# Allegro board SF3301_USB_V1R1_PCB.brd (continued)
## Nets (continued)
0: C13.1 C14.2 C15.2 C18.2 C20.2 C22.1 C23.2 C25.2 C26.2 C27.1 C28.1 C29.1 C30.1 C31.1 C32.1 C33.1 C44.2 C45.2 C46.2 C47.2 C48.2 C49.2 C50.2 C51.2 C62.2 C63.2 C64.2 C65.2 C66.2 C67.2 C68.2 C69.2 C70.2 C71.2 C72.2 C73.2 C74.2 C75.2 C76.2 C77.2 C78.2 C79.2 C80.2 C81.2 C82.2 C83.2 C84.2 C85.2 C86.2 C87.2 C88.2 C89.2 C90.2 C91.2 C92.2 C93.2 C94.2 C95.2 C96.2 C97.2 C98.2 C99.2 C100.2 C101.2 C102.2 C103.2 C104.2 C105.2 C106.2 C107.2 C108.2 C109.2 C110.2 C111.2 C112.2 C113.2 C114.2 C115.2 C116.2 C117.2 C118.2 C119.2 C120.2 C121.2 C122.2 C123.2 C124.2 C125.2 C126.2 C127.2 C128.2 C129.2 C130.2 C131.2 C132.2 C133.2 C134.2 C135.2 C136.2 C137.2 C138.2 C139.2 C140.2 C141.2 C142.2 C143.2 C144.2 C145.2 C146.2 C147.2 C148.2 C149.2 C150.2 C201.2 C202.2 C203.2 C204.2 C205.2 C206.2 C207.2 C208.2 C209.2 C210.2 C211.2 C212.2 C213.2 C214.2 C215.2 C216.2 C217.2 C218.2 C219.2 C220.2 C221.2 C222.2 C223.2 C224.2 C225.2 C226.2 C227.2 C228.2 C229.2 C230.2 C231.2 C232.2 C233.2 C234.2 C235.2 C236.2 C237.2 C238.2 C239.2 C240.2 C241.2 C242.2 C243.2 C244.2 C245.2 C246.2 C247.2 C248.2 C249.1 C250.1 C252.1 C253.1 C254.2 C255.2 C256.2 C257.2 C258.1 C260.1 C261.1 C262.1 C263.1 C264.2 C265.2 C270.1 C272.1 C273.1 C274.1 C275.1 C276.1 C278.2 C279.1 C281.1 C285.1 C287.2 C288.1 C289.1 C290.1 C291.2 C292.1 C294.1 C297.2 C298.2 C299.2 C300.2 C301.2 C302.2 C303.2 C304.2 C305.2 C306.2 C307.2 C308.2 C309.2 C310.2 C311.2 C312.2 C313.2 C314.2 C315.2 C316.2 C318.2 C319.2 C320.2 C321.1 C323.2 C324.2 C325.2 C326.2 C327.2 C328.2 C329.2 C330.2 C331.2 C333.2 C350.2 C351.2 C352.2 C353.1 C354.1 C355.1 C356.1 C357.1 C358.1 C359.2 C360.2 C363.1 C365.1 C366.2 C370.1 C372.1 C375.1 C376.1 C377.1 C378.1 C379.1 C380.1 C381.1 C387.2 C390.1 C391.1 C392.2 CP1.2 CP2.2 CP3.2 CP4.2 CP5.2 CP6.2 CP7.2 CP8.2 D2.1(A) D13.2(CATHODE) D14.2(CATHODE) D15.2(CATHODE) D16.2(CATHODE) D17.2(CATHODE) D18.2(CATHODE) D24.2(CATHODE) D25.2(CATHODE) ER2.2 ER3.2 FB7.2(FB2) FB9.2(FB2) FB11.2(FB2) J2.2 J3.5(GND) J9.1(GND1) J9.2(GND2) J10.2 J10.3 J11.1 Q3.2 Q6.1 Q6.2 Q6.3 Q7.1 Q7.2 Q7.3 Q10.1 Q10.2 Q10.3 Q11.1 Q11.2 Q11.3 Q14.1 Q14.2 Q14.3 Q15.1 Q15.2 Q15.3 Q18.1 Q18.2 Q18.3 Q19.1 Q19.2 Q19.3 Q21.1 Q21.2 Q21.3 Q23.S Q24.2 Q25.2 Q26.2 Q27.2 Q28.2 R44.2 R59.2 R60.2 R63.1 R67.2 R75.2 R77.2 R82.1 R99.1 R103.1 R107.2 R108.1 R115.1 R118.1 R122.1 R129.1 R131.1 R133.1 R135.1 R137.1 R139.1 R154.2 R191.1 R193.1 R194.1 R195.1 R196.1 R197.1 R198.1 R199.1 R203.1 R208.1 R210.1 R214.1 R217.1 R219.1 R223.1 R227.2 R241.2 R243.2 R247.1 SW1.1 SW1.3 SW1.4 TC2.2 TC3.2 TC4.2 TC5.2 TC6.2 TP3.1(PIN1) TP4.1(PIN1) TP9.1(PIN1) U3.1(GND) U5.A1(BTC_GND1) U5.A3(BTC_GND17) U5.A5(BTC_GND34) U5.A7(BTC_GND43) U5.A9(BTC_GND56) U5.A11(BTC_GND69) U5.A13(BTC_GND82) U5.A15(BTC_GND95) U5.A17(BTC_GND108) U5.A19(BTC_GND116) U5.A23(BTC_GND141) U5.AA1(LTC_GND2) U5.AA3(LTC_GND8) U5.AA5(LTC_GND16) U5.AA7(LTC_GND23) U5.AA9(LTC_GND31) U5.AA11(LTC_GND39) U5.AA13(LTC_GND47) U5.AA15(LTC_GND55) U5.AA17(LTC_GND63) U5.AA19(LTC_GND69) U5.AA21(LTC_GND78) U5.AA22(GNDE5) U5.AB2(LTC_GND6) U5.AB4(LTC_GND12) U5.AB6(LTC_GND19) U5.AB8(LTC_GND27) U5.AB10(LTC_GND35) U5.AB12(LTC_GND43) U5.AB14(LTC_GND51) U5.AB16(LTC_GND59) U5.AB18(LTC_GND66) U5.AB20(LTC_GND74) U5.AC1(LTC_GND3) U5.AC3(LTC_GND9) U5.AC5(LTC_GND17) U5.AC7(LTC_GND24) U5.AC9(LTC_GND32) U5.AC11(LTC_GND40) U5.AC13(LTC_GND48) U5.AC15(LTC_GND56) U5.AC17(LTC_GND64) U5.AC19(LTC_GND70) U5.AC21(LTC_GND79) U5.AC22(GNDE6) U5.B2(BTC_GND10) U5.B4(BTC_GND26) U5.B6(BTC_GND41) U5.B8(BTC_GND50) U5.B10(BTC_GND63) U5.B12(BTC_GND76) U5.B14(BTC_GND89) U5.B16(BTC_GND102) U5.B18(BTC_GND114) U5.B20(BTC_GND124) U5.B21(ESDSUB_ANA4) U5.B22(ESDSUB_ANA3) U5.C1(BTC_GND2) U5.C3(BTC_GND18) U5.C5(BTC_GND35) U5.C7(BTC_GND44) U5.C9(BTC_GND57) U5.C11(BTC_GND70) U5.C13(BTC_GND83) U5.C15(BTC_GND96) U5.C17(BTC_GND109) U5.C19(BTC_GND117) U5.C21(BTC_GND131) U5.C22(ESDSUB_ANA2) U5.C23(BTC_GND142) U5.D2(BTC_GND11) U5.D4(BTC_GND27) U5.D6(BTC_GND42) U5.D8(BTC_GND51) U5.D10(BTC_GND64) U5.D12(BTC_GND77) U5.D14(BTC_GND90) U5.D16(BTC_GND103) U5.D18(BTC_GND115) U5.D20(BTC_GND125) U5.D22(ESDSUB_ANA1) U5.D23(BTC_GND143) U5.E1(BTC_GND3) U5.E3(BTC_GND19) U5.E5(BTC_GND36) U5.E7(BTC_GND45) U5.E9(BTC_GND58) U5.E11(BTC_GND71) U5.E13(BTC_GND84) U5.E15(BTC_GND97) U5.E17(BTC_GND110) U5.E19(BTC_GND118) U5.E21(BTC_GND132) U5.E22(BTC_GND138) U5.F2(BTC_GND12) U5.F4(BTC_GND28) U5.F20(BTC_GND126) U5.F21(AGNDSUB_OSC) U5.F22(GNDA_OSC) U5.G1(BTC_GND4) U5.G3(BTC_GND20) U5.G5(BTC_GND37) U5.G7(BTC_GND46) U5.G9(BTC_GND59) U5.G11(BTC_GND72) U5.G13(BTC_GND85) U5.G15(BTC_GND98) U5.G17(BTC_GND111) U5.G19(BTC_GND119) U5.G21(BTC_GND133) U5.H2(BTC_GND13) U5.H4(BTC_GND29) U5.H8(BTC_GND52) U5.H10(BTC_GND65) U5.H12(BTC_GND78) U5.H14(BTC_GND91) U5.H16(BTC_GND104) U5.H20(BTC_GND127) U5.H22(BTC_GND139) U5.H23(GNDE7) U5.J1(BTC_GND5) U5.J3(BTC_GND21) U5.J5(BTC_GND38) U5.J7(BTC_GND47) U5.J9(BTC_GND60) U5.J11(BTC_GND73) U5.J13(BTC_GND86) U5.J15(BTC_GND99) U5.J17(BTC_GND112) U5.J19(BTC_GND120) U5.J21(BTC_GND134) U5.K2(BTC_GND14) U5.K4(BTC_GND30) U5.K8(BTC_GND53) U5.K10(BTC_GND66) U5.K12(BTC_GND79) U5.K14(BTC_GND92) U5.K16(BTC_GND105) U5.K20(BTC_GND128) U5.K22(GNDE1) U5.L1(BTC_GND6) U5.L3(BTC_GND22) U5.L5(BTC_GND39) U5.L7(BTC_GND48) U5.L9(BTC_GND61) U5.L11(BTC_GND74) U5.L13(BTC_GND87) U5.L15(BTC_GND100) U5.L17(BTC_GND113) U5.L19(BTC_GND121) U5.L21(BTC_GND135) U5.M2(BTC_GND15) U5.M4(BTC_GND31) U5.M8(BTC_GND54) U5.M10(BTC_GND67) U5.M12(BTC_GND80) U5.M14(BTC_GND93) U5.M16(BTC_GND106) U5.M19(BTC_GND122) U5.M20(BTC_GND129) U5.M22(BTC_GND140) U5.N1(BTC_GND7) U5.N3(BTC_GND23) U5.N5(BTC_GND40) U5.N7(BTC_GND49) U5.N9(BTC_GND62) U5.N11(BTC_GND75) U5.N13(BTC_GND88) U5.N15(BTC_GND101) U5.N21(BTC_GND136) U5.P4(BTC_GND32) U5.P8(BTC_GND55) U5.P10(BTC_GND68) U5.P12(BTC_GND81) U5.P14(BTC_GND94) U5.P16(BTC_GND107) U5.P21(BTC_GND137) U5.P22(GNDE2) U5.R1(BTC_GND8) U5.R3(BTC_GND24) U5.R5(LTC_GND13) U5.R7(LTC_GND20) U5.R9(LTC_GND28) U5.R11(LTC_GND36) U5.R13(LTC_GND44) U5.R15(LTC_GND52) U5.R17(LTC_GND60) U5.R19(BTC_GND123) U5.R20(BTC_GND130) U5.R21(LTC_GND75) U5.T2(BTC_GND16) U5.T4(BTC_GND33) U5.T8(LTC_GND25) U5.T10(LTC_GND33) U5.T12(LTC_GND41) U5.T14(LTC_GND49) U5.T16(LTC_GND57) U5.T20(LTC_GND71) U5.T22(GNDE3) U5.U1(BTC_GND9) U5.U3(BTC_GND25) U5.U5(LTC_GND14) U5.U7(LTC_GND21) U5.U9(LTC_GND29) U5.U11(LTC_GND37) U5.U13(LTC_GND45) U5.U15(LTC_GND53) U5.U17(LTC_GND61) U5.U19(LTC_GND67) U5.U21(LTC_GND76) U5.V2(LTC_GND4) U5.V4(LTC_GND10) U5.V20(LTC_GND72) U5.V22(LTC_GND80) U5.W1(LTC_GND1) U5.W3(LTC_GND7) U5.W5(LTC_GND15) U5.W7(LTC_GND22) U5.W9(LTC_GND30) U5.W11(LTC_GND38) U5.W13(LTC_GND46) U5.W15(LTC_GND54) U5.W17(LTC_GND62) U5.W19(LTC_GND68) U5.W21(LTC_GND77) U5.Y2(LTC_GND5) U5.Y4(LTC_GND11) U5.Y6(LTC_GND18) U5.Y8(LTC_GND26) U5.Y10(LTC_GND34) U5.Y12(LTC_GND42) U5.Y14(LTC_GND50) U5.Y16(LTC_GND58) U5.Y18(LTC_GND65) U5.Y20(LTC_GND73) U5.Y22(GNDE4) U6.11(GND) U7.2(GND) U8.6(GND) U9.6(GND) U10.6(GND) U11.41(PAD) U12.6(GND) U13.33(GND) U14.3(GND) U14.6(LV) U18.1(VSS) U19.2(GND) U19.25(PAD) U20.4(GND) U20.9(THER) X1.2(GND)
6314_ISEN: C361.2 L6.2 Q20.1(SOURCE1) Q20.2(SOURCE2) Q20.3(SOURCE3) Q21.5 Q21.6 Q21.7 Q21.8 R190.1 R201.2 R202.1 U13.24(PHASE)
6314_ISEN-: C362.1 C364.2 R202.2 R204.2 U13.15(ISEN-)
ADJ_TP: C276.2 R59.1 R60.1 R76.2
BTC_GNDS_0: C38.1 J6.1 J6.3 J6.5 U5.A20(BTC_GNDS_0)
BTC_GNDS_1: C39.1 J8.1 J8.3 J8.5 U5.P1(BTC_GNDS_1)
BTC_PGD: R127.2 R152.2 R181.2 R233.2
BTC_VDD: C46.1 C47.1 C48.1 C49.1 C50.1 C51.1 C62.1 C63.1 C64.1 C65.1 C66.1 C67.1 C68.1 C69.1 C70.1 C71.1 C72.1 C73.1 C74.1 C75.1 C76.1 C77.1 C78.1 C79.1 C80.1 C81.1 C82.1 C83.1 C84.1 C85.1 C86.1 C87.1 C88.1 C89.1 C90.1 C91.1 C92.1 C93.1 C94.1 C95.1 C96.1 C97.1 C98.1 C99.1 C100.1 C101.1 C102.1 C103.1 C104.1 C105.1 C106.1 C107.1 C108.1 C109.1 C110.1 C111.1 C112.1 C113.1 C114.1 C115.1 C116.1 C117.1 C118.1 C119.1 C120.1 C121.1 C122.1 C123.1 C124.1 C125.1 C126.1 C127.1 C128.1 C129.1 C130.1 C131.1 C132.1 C133.1 C134.1 C135.1 C136.1 C137.1 C138.1 C139.1 C140.1 C141.1 C142.1 C143.1 C144.1 C145.1 C146.1 C147.1 C148.1 C149.1 C150.1 C280.1 C282.1 C283.1 C284.1 C297.1 C298.1 C299.1 C300.1 C301.1 C302.1 C303.1 C304.1 C305.1 C306.1 C307.1 C308.1 C309.1 C310.1 C311.1 C312.1 C313.1 C314.1 C315.1 C316.1 CP3.1 CP4.1 CP5.1 CP6.1 D6.A L1.1 L3.1 L4.1 L5.1 R70.1 R89.1 R92.1 R95.1 TC2.1 TC3.1 TC4.1 TC5.1 U5.A2(BTC_VDD8) U5.A4(BTC_VDD25) U5.A6(BTC_VDD41) U5.A8(BTC_VDD50) U5.A10(BTC_VDD63) U5.A12(BTC_VDD76) U5.A14(BTC_VDD89) U5.A16(BTC_VDD102) U5.A18(BTC_VDD116) U5.B1(BTC_VDD1) U5.B3(BTC_VDD17) U5.B5(BTC_VDD34) U5.B7(BTC_VDD44) U5.B9(BTC_VDD57) U5.B11(BTC_VDD70) U5.B13(BTC_VDD83) U5.B15(BTC_VDD96) U5.B17(BTC_VDD109) U5.B19(BTC_VDD119) U5.C2(BTC_VDD9) U5.C4(BTC_VDD26) U5.C6(BTC_VDD42) U5.C8(BTC_VDD51) U5.C10(BTC_VDD64) U5.C12(BTC_VDD77) U5.C14(BTC_VDD90) U5.C16(BTC_VDD103) U5.C18(BTC_VDD117) U5.C20(BTC_VDD124) U5.D1(BTC_VDD2) U5.D3(BTC_VDD18) U5.D5(BTC_VDD35) U5.D7(BTC_VDD45) U5.D9(BTC_VDD58) U5.D11(BTC_VDD71) U5.D13(BTC_VDD84) U5.D15(BTC_VDD97) U5.D17(BTC_VDD110) U5.D19(BTC_VDD120) U5.D21(BTC_VDD129) U5.E2(BTC_VDD10) U5.E4(BTC_VDD27) U5.E6(BTC_VDD43) U5.E8(BTC_VDD52) U5.E10(BTC_VDD65) U5.E12(BTC_VDD78) U5.E14(BTC_VDD91) U5.E16(BTC_VDD104) U5.E18(BTC_VDD118) U5.E20(BTC_VDD125) U5.F1(BTC_VDD3) U5.F3(BTC_VDD19) U5.F5(BTC_VDD36) U5.F19(BTC_VDD121) U5.G2(BTC_VDD11) U5.G4(BTC_VDD28) U5.G8(BTC_VDD53) U5.G10(BTC_VDD66) U5.G12(BTC_VDD79) U5.G14(BTC_VDD92) U5.G16(BTC_VDD105) U5.G20(BTC_VDD126) U5.H1(BTC_VDD4) U5.H3(BTC_VDD20) U5.H5(BTC_VDD37) U5.H7(BTC_VDD46) U5.H9(BTC_VDD59) U5.H11(BTC_VDD72) U5.H13(BTC_VDD85) U5.H15(BTC_VDD98) U5.H17(BTC_VDD111) U5.H19(BTC_VDD122) U5.H21(BTC_VDD130) U5.J2(BTC_VDD12) U5.J4(BTC_VDD29) U5.J8(BTC_VDD54) U5.J10(BTC_VDD67) U5.J12(BTC_VDD80) U5.J14(BTC_VDD93) U5.J16(BTC_VDD106) U5.J20(BTC_VDD127) U5.K1(BTC_VDD5) U5.K3(BTC_VDD21) U5.K5(BTC_VDD38) U5.K7(BTC_VDD47) U5.K9(BTC_VDD60) U5.K11(BTC_VDD73) U5.K13(BTC_VDD86) U5.K15(BTC_VDD99) U5.K17(BTC_VDD112) U5.K19(BTC_VDD123) U5.K21(BTC_VDD131) U5.L2(BTC_VDD13) U5.L4(BTC_VDD30) U5.L8(BTC_VDD55) U5.L10(BTC_VDD68) U5.L12(BTC_VDD81) U5.L14(BTC_VDD94) U5.L16(BTC_VDD107) U5.L20(BTC_VDD128) U5.M1(BTC_VDD6) U5.M3(BTC_VDD22) U5.M5(BTC_VDD39) U5.M7(BTC_VDD48) U5.M9(BTC_VDD61) U5.M11(BTC_VDD74) U5.M13(BTC_VDD87) U5.M15(BTC_VDD100) U5.M17(BTC_VDD113) U5.M21(BTC_VDD132) U5.N2(BTC_VDD14) U5.N4(BTC_VDD31) U5.N8(BTC_VDD56) U5.N10(BTC_VDD69) U5.N12(BTC_VDD82) U5.N14(BTC_VDD95) U5.N16(BTC_VDD108) U5.N17(BTC_VDD114) U5.N22(BTC_VDD133) U5.P3(BTC_VDD23) U5.P5(BTC_VDD40) U5.P7(BTC_VDD49) U5.P9(BTC_VDD62) U5.P11(BTC_VDD75) U5.P13(BTC_VDD88) U5.P15(BTC_VDD101) U5.P17(BTC_VDD115) U5.R2(BTC_VDD15) U5.R4(BTC_VDD32) U5.T1(BTC_VDD7) U5.T3(BTC_VDD24) U5.U2(BTC_VDD16) U5.U4(BTC_VDD33)
BTC_VDDS_0: C38.2 J5.1 J5.3 J5.5 U5.A21(BTC_VDDS_0)
BTC_VDDS_1: C39.2 J7.1 J7.3 J7.5 U5.P2(BTC_VDDS_1)
DNRX0: R25.2 R33.1 U5.R22(DNRX0)
DNRX1: R27.2 R41.1 U5.U23(DNRX1)
DNTX0: R26.2 R35.1 U5.R23(DNTX0)
DNTX1: R29.2 R37.1 U5.U22(DNTX1)
FB_VSS: C271.1 R122.2 U11.3(FBRTN)
ISL6314_VID0: R199.2 U13.31(VID0)
ISL6314_VID1: R198.2 U13.30(VID1)
ISL6314_VID2: R197.2 U13.29(VID2)
ISL6314_VID3: R196.2 U13.28(VID3)
ISL6314_VID4: R195.2 U13.27(VID4)
ISL6314_VID5: R194.2 U13.26(VID5)
ISL6314_VID6: R193.2 U13.25(VID6)
ISL6314_VID7: R191.2 U13.32(VID7)
ISN1: R85.2 R95.2 U11.18(ISN1)
ISN24: R87.2 R92.2 U11.19(ISN24)
ISN35: R79.2 R89.2 U11.20(ISN35)
ISP1: C284.2 R96.2 U11.25(ISP1)
ISP2: C283.2 R93.2 U11.24(ISP2)
ISP3: C282.2 R90.2 U11.23(ISP3)
ISP4: C280.2 R86.2 U11.22(ISP4)
ISP5: R103.2 U11.21(ISP5)
LTC_PGD: R110.2 R173.1
LTC_PGD_R: C359.1 R143.2 R173.2 U13.1(PGOOD)
LTC_VDD: C201.1 C202.1 C203.1 C204.1 C205.1 C206.1 C207.1 C208.1 C209.1 C210.1 C211.1 C212.1 C213.1 C214.1 C215.1 C216.1 C217.1 C218.1 C219.1 C220.1 C221.1 C222.1 C223.1 C224.1 C225.1 C226.1 C227.1 C228.1 C229.1 C230.1 C231.1 C232.1 C233.1 C234.1 C235.1 C236.1 C237.1 C238.1 C239.1 C240.1 C241.1 C242.1 C243.1 C244.1 C245.1 C246.1 C247.1 C248.1 C323.1 C324.1 C325.1 C362.2 C365.2 CP7.1 L6.1 R206.1 R208.2 TC6.1 U5.AA2(LTC_VDD5) U5.AA4(LTC_VDD11) U5.AA6(LTC_VDD18) U5.AA8(LTC_VDD26) U5.AA10(LTC_VDD34) U5.AA12(LTC_VDD42) U5.AA14(LTC_VDD50) U5.AA16(LTC_VDD58) U5.AA18(LTC_VDD64) U5.AA20(LTC_VDD72) U5.AB1(LTC_VDD3) U5.AB3(LTC_VDD9) U5.AB5(LTC_VDD16) U5.AB7(LTC_VDD22) U5.AB9(LTC_VDD30) U5.AB11(LTC_VDD38) U5.AB13(LTC_VDD46) U5.AB15(LTC_VDD54) U5.AB17(LTC_VDD62) U5.AB19(LTC_VDD69) U5.AB21(LTC_VDD77) U5.AC2(LTC_VDD6) U5.AC4(LTC_VDD12) U5.AC6(LTC_VDD19) U5.AC8(LTC_VDD27) U5.AC10(LTC_VDD35) U5.AC12(LTC_VDD43) U5.AC14(LTC_VDD51) U5.AC16(LTC_VDD59) U5.AC18(LTC_VDD65) U5.AC20(LTC_VDD73) U5.R8(LTC_VDD23) U5.R10(LTC_VDD31) U5.R12(LTC_VDD39) U5.R14(LTC_VDD47) U5.R16(LTC_VDD55) U5.T5(LTC_VDD13) U5.T7(LTC_VDD20) U5.T9(LTC_VDD28) U5.T11(LTC_VDD36) U5.T13(LTC_VDD44) U5.T15(LTC_VDD52) U5.T17(LTC_VDD60) U5.T19(LTC_VDD66) U5.T21(LTC_VDD74) U5.U8(LTC_VDD24) U5.U10(LTC_VDD32) U5.U12(LTC_VDD40) U5.U14(LTC_VDD48) U5.U16(LTC_VDD56) U5.U20(LTC_VDD70) U5.V1(LTC_VDD1) U5.V3(LTC_VDD7) U5.V5(LTC_VDD14) U5.V19(LTC_VDD67) U5.V21(LTC_VDD75) U5.W2(LTC_VDD4) U5.W4(LTC_VDD10) U5.W6(LTC_VDD17) U5.W8(LTC_VDD25) U5.W10(LTC_VDD33) U5.W12(LTC_VDD41) U5.W14(LTC_VDD49) U5.W16(LTC_VDD57) U5.W18(LTC_VDD63) U5.W20(LTC_VDD71) U5.W22(LTC_VDD78) U5.Y1(LTC_VDD2) U5.Y3(LTC_VDD8) U5.Y5(LTC_VDD15) U5.Y7(LTC_VDD21) U5.Y9(LTC_VDD29) U5.Y11(LTC_VDD37) U5.Y13(LTC_VDD45) U5.Y15(LTC_VDD53) U5.Y17(LTC_VDD61) U5.Y19(LTC_VDD68) U5.Y21(LTC_VDD76) U13.16(ISEN+)
OSC_BP: R39.1 R44.1 U5.P23(OSC_BP)
OSC_EN: C354.2 Q24.3 R183.1 R186.2 X1.1(OE)
OSC_ZO: R38.2 U5.E23(OSC_ZO)
PSU_12V: C255.1 C256.1 C326.1 D8.A J9.3(12V_1) J9.4(12V_2) L2.2
PWM1: U8.2(PWM) U11.26(PWM1)
PWM2: U9.2(PWM) U11.27(PWM2)
PWM3: U10.2(PWM) U11.28(PWM3)
PWM4: U11.29(PWM4) U12.2(PWM)
PWM5: R83.2 U11.30(PWM5)
RST_SF3301: C356.2 D19.A Q26.3 R28.2 R220.2 SW1.2 U5.M23(RSTN)
RT8802A_PHASE1: C251.1 L1.2 Q4.1(SOURCE1) Q4.2(SOURCE2) Q4.3(SOURCE3) Q5.1(SOURCE1) Q5.2(SOURCE2) Q5.3(SOURCE3) Q6.5 Q6.6 Q6.7 Q6.8 Q7.5 Q7.6 Q7.7 Q7.8 R61.2 R96.1 U8.7(PHASE)
RT8802A_PHASE2: C259.1 L3.2 Q8.1(SOURCE1) Q8.2(SOURCE2) Q8.3(SOURCE3) Q9.1(SOURCE1) Q9.2(SOURCE2) Q9.3(SOURCE3) Q10.5 Q10.6 Q10.7 Q10.8 Q11.5 Q11.6 Q11.7 Q11.8 R66.2 R93.1 U9.7(PHASE)
RT8802A_PHASE3: C277.1 L4.2 Q12.1(SOURCE1) Q12.2(SOURCE2) Q12.3(SOURCE3) Q13.1(SOURCE1) Q13.2(SOURCE2) Q13.3(SOURCE3) Q14.5 Q14.6 Q14.7 Q14.8 Q15.5 Q15.6 Q15.7 Q15.8 R78.2 R90.1 U10.7(PHASE)
RT8802A_PHASE4: C286.1 L5.2 Q16.1(SOURCE1) Q16.2(SOURCE2) Q16.3(SOURCE3) Q17.1(SOURCE1) Q17.2(SOURCE2) Q17.3(SOURCE3) Q18.5 Q18.6 Q18.7 Q18.8 Q19.5 Q19.6 Q19.7 Q19.8 R86.1 R109.2 U12.7(PHASE)
RUN_LED: D1.C1 U19.22(GPIO.2_SCI/RSR_SCI)
UART1_RX: R49.2 U6.3(A2)
UART1_RX_3V3: R9.2 U19.12(RXD_ECI)
UART1_TX: R48.2 U6.1(A1)
UART1_TX_3V3: R8.2 U19.13(TXD_ECI)
UART2_RX: R51.2 U6.5(A4)
UART2_RX_3V3: R11.2 U19.20(RXD_SCI)
UART2_TX: R50.2 U6.4(A3)
UART2_TX_3V3: R10.2 U19.21(TXD_SCI)
UPRX0: R48.1 R174.2 U5.J22(UPRX0)
UPRX1: R50.1 R175.2 U5.L23(UPRX1)
UPTX0: R46.2 R49.1 U5.J23(UPTX0)
UPTX1: R47.2 R51.1 U5.L22(UPTX1)
USB_DM: R23.1 U19.4(D-)
USB_DP: R24.1 U19.3(D+)
VCORE: D6.C R79.1 R82.2 R85.1 R87.1
VID0: R80.1 R128.1 R129.2 U11.39(VID0)
VID1: R81.1 R130.1 R131.2 U11.38(VID1)
VID2: R88.1 R132.1 R133.2 U11.37(VID2)
VID3: R91.1 R134.1 R135.2 U11.36(VID3)
VID4: R94.1 R136.1 R137.2 U11.35(VID4)
VID5: R97.1 R138.1 R139.2 U11.34(VID5)
VID6: R98.1 R244.1 R247.2 U11.33(VID6)
VID7: R99.2 R245.1 R248.1 U11.32(VID7)
XCLKIN: R184.1 R185.2 U5.F23(XCLKIN)
N16884499: C18.1 R32.1 R185.1 Y2.2
N16884503: C20.1 R32.2 R38.1 Y2.1
N16885409: TP10.1(PIN1) U5.V23(DBG)
N16885936: R178.2 U5.K23(XCLKOUT)
N16887961: R45.2 U5.AA23(ANAREXTPAD)
N16887964: ER2.1 R45.1 U5.AB23(GNDBGCOMP)
N16971828: Q6.4(GATE) Q7.4(GATE) U8.5(LGATE)
N16972086: Q10.4(GATE) Q11.4(GATE) U9.5(LGATE)
N16972137: Q8.4(GATE) Q9.4(GATE) U9.8(UGATE)
N16972188: C267.2 R68.2 U11.5(COMP)
N16972208: C268.2 R68.1
N16972210: C267.1 C268.1 C269.2 R69.2 U11.4(FB)
N16972290: C287.1 R102.1 U11.31(VDD)
N16972304: C270.2 R66.1
N16972345: C265.1 U11.6(SS)
N16972387: R67.1 R71.2 U11.16(TCOC)
N16972391: D4.C R65.2 U9.1(BOOT)
N16972393: C264.1 D4.A R64.1 U9.4(VCC)
N16972419: R71.1 U11.17(IMAX)
N16972439: Q4.4(GATE) Q5.4(GATE) U8.8(UGATE)
N16972492: C259.2 R65.1
N16972578: R115.2 U11.7(QRSEL)
N16972692: C292.2 R105.2 U11.10(TSET)
N16972744: Q14.4(GATE) Q15.4(GATE) U10.5(LGATE)
N16972799: Q12.4(GATE) Q13.4(GATE) U10.8(UGATE)
N16972986: C281.2 R78.1
N16973045: D5.C R72.2 U10.1(BOOT)
N16973047: C278.1 D5.A R73.1 U10.4(VCC)
N16973105: C277.2 R72.1
N16973186: D14.1(ANODE) R130.2
N16973189: D13.1(ANODE) R128.2
N16973192: D15.1(ANODE) R132.2
N16973195: D16.1(ANODE) R134.2
N16973214: D17.1(ANODE) R136.2
N16973217: D18.1(ANODE) R138.2
N16973302: C269.1 C271.2 R69.1 R70.2
N16973383: R76.1 U11.15(ADJ)
N16973403: R108.2 U11.11(IOUT)
N16973441: C258.2 R61.1
N16973681: R75.1 U11.13(RT)
N16974286: R116.2 R118.2 U11.14(OFS)
N16974990: D3.C R58.2 U8.1(BOOT)
N16975003: C254.1 D3.A R57.1 U8.4(VCC)
N16975056: R104.1 R107.1 U11.12(DVD)
N16975081: R126.1 R127.1 U11.2(VR_READY)
N16975136: R110.1 R124.2 R125.2 R126.2 U11.1(VTTEN)
N16975276: C251.2 R58.1
N16975672: R124.1 U11.9(VR_HOT)
N16975684: R125.1 U11.8(VR_FAN)
N17005585: C279.2 R77.1 R84.1 U11.40(VID_SEL)
N17031806: C344.1 D9.3(CA) D9.4(REF) R161.1 R162.2
N17031808: R155.1 R156.2 U16.2(IN-)
N17031818: R156.1 R159.2 U16.1(OUT)
N17031906: C338.1 R162.1 R165.1 U16.3(IN+) U16.5(IN+)
N17032029: R169.2 R179.1 U16.7(OUT)
N17032033: R167.1 R179.2 U16.6(IN-)
N17032770: R170.2 R180.1 U17.7(OUT)
N17034652: C327.1 D8.C J11.2
N17047933: C332.1 U14.2(CAP+)
N17047953: C332.2 U14.4(CAP-)
N17253373: R157.1 R158.2 U17.2(IN-)
N17253375: R158.1 R160.2 U17.1(OUT)
N17253408: C340.1 R164.1 R166.1 U17.3(IN+) U17.5(IN+)
N17253441: R168.1 R180.2 U17.6(IN-)
N17254276: C345.1 D10.3(CA) D10.4(REF) R163.1 R164.2
N17260942: Q22.1(GATE) R151.1
N17260992: Q23.D R150.1 R151.2
N17261273: Q23.G R152.1 R154.1
N17354264: Q18.4(GATE) Q19.4(GATE) U12.5(LGATE)
N17354299: Q16.4(GATE) Q17.4(GATE) U12.8(UGATE)
N17354448: C294.2 R109.1
N17354514: D7.C R100.2 U12.1(BOOT)
N17354516: C291.1 D7.A R101.1 U12.4(VCC)
N17354559: C286.2 R100.1
N17460832: D2.3(C2) J3.2(DM) R23.2
N17460836: D2.2(C1) J3.3(DP) R24.2
N17465473: R178.1 TP8.1(PIN1)
N17472139: R205.1 U13.13(OCSET)
N17472149: C364.1 R204.1 R205.2 U13.14(ISENNO)
N17472208: R207.1 R209.1 U13.10(VDIFF)
N17472210: C367.1 R207.2
N17472223: C367.2 C369.2 C371.2 C374.2 R209.2 R212.2
N17472242: C366.1 C368.2 R206.2 U13.12(VSEN)
N17472254: R211.1 U13.8(DVC)
N17472271: C369.1 R211.2
N17472288: R212.1 U13.9(FB)
N17472302: C371.1 C373.2 R215.1 R218.2 U13.7(COMP)
N17472317: C373.1 R218.1 U13.6(APA)
N17472378: C368.1 C370.2 R210.2 U13.11(RGND)
N17472408: R213.2 R214.2 U13.5(OFS)
N17472451: C372.2 U13.4(REF)
N17472474: R216.2 R217.2 U13.3(FS)
N17472541: C358.2 C391.2 R188.1 U13.19(PVCC)
N17472572: R192.1 U13.22(BOOT)
N17472629: R189.1 U13.23(UGATE)
N17472645: R200.1 U13.21(LGATE)
N17472992: C360.1 R141.2 U13.17(EN)
N17485645: R219.2 U13.2(SS)
N17488147: C361.1 R192.2
N17489529: C374.1 R215.2
N17492409: Q21.4(GATE) R200.2 R203.2
N17495070: Q20.4(GATE) R189.2 R190.2
N17497213: C363.2 R201.1
N17500314: R30.2 R233.1 U18.2(R\S\T\)
N17502184: R181.1 U18.3(M\R\)
N17503406: C353.2 Q3.1 R30.1
N17507007: Q3.3 Q24.1 R182.1
N17511574: R184.2 X1.3(OUT)
N17512182: C351.1 C352.1 FB10.1(FB1) X1.4(VDD)
N17523163: C355.2 Q25.1 R186.1
N17523415: Q25.3 Q26.1 R187.1
N17532743: R11.1 R177.1 U6.16(B4)
N17532745: R10.1 R176.1 U6.17(B3)
N17532747: R9.1 R14.1 U6.18(B2)
N17532758: R8.1 R13.1 U6.20(B1)
N17535586: R33.2 U6.6(A5)
N17535589: R35.2 U6.7(A6)
N17535592: R41.2 U6.8(A7)
N17535595: R37.2 U6.9(A8)
N17535696: R34.1 U6.15(B5)
N17535699: R40.1 U6.14(B6)
N17535702: R36.1 U6.13(B7)
N17535705: R42.1 U6.12(B8)
N17535726: J4.1 R34.2
N17535729: J4.2 R40.2
N17535732: J4.3 R36.2
N17535735: J4.4 R42.2
N17540184: C375.2 Q27.1 R220.1
N17540190: D1.A2 Q28.3 R222.1
N17540204: Q27.3 Q28.1 R221.1
N17540688: D1.C2 R223.2
N17540854: D1.A1 R224.1
N17542536: C378.2 U19.16(NC/DCD_ECI/VPP)
N17542621: C379.2 J2.1 R225.1 U19.9(R\S\T\)
N17543309: C381.2 R226.1 R227.1 U19.8(VBUS)
N17544610: D20.2(CATHODE) U19.24(GPIO.0/DCD_SCI)
N17544613: D20.1(ANODE) R228.2
N17544663: D21.2(CATHODE) U19.23(GPIO.1_SCI/RTR_SCI)
N17544665: D21.1(ANODE) R229.2
N17544725: D22.2(CATHODE) U19.15(GPIO.0_ECI/DTR_ECI)
N17544727: D22.1(ANODE) R230.2
N17544738: D23.2(CATHODE) U19.14(GPIO.1_ECI/DSR_ECI)
N17544740: D23.1(ANODE) R231.2
N17552651: J10.1(PIN) R62.1 R63.2
N17568086: R232.2 U6.10(OE)
N17581232: R240.1 U20.7(EN)
N17581329: C390.2 U20.8(SS)
N17581616: C388.1 U20.1(BS)
N17581619: C388.2 L8.2 U20.3(LX)
N17581966: C389.1 U20.6(COMP)
N17581969: C389.2 R241.1
N17582251: R242.2 R243.1 U20.5(FB)
N17600922: D24.1(ANODE) R244.2
N17601217: D25.1(ANODE) R245.2

Pads without a net: D9 1 2; D10 1 2; H1 1; H2 1; H3 1; H4 1; J3 4; J11 3; NOREF 1; NOREF#3 1; NOREF#6 1; NOREF#7 1; NOREF#8 1; NOREF#9 1; U7 4; U8 3; U9 3; U10 3; U12 3; U13 20; U14 1 7; U19 1 10 11 17 18 19

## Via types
v1: diameter 0.559, hole 0.254, TOP to BOTTOM, 1641 vias
v2: diameter 0.406, hole 0.203, TOP to BOTTOM, 325 vias

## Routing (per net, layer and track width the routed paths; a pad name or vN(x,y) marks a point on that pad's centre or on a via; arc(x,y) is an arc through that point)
AGND_THS: length 3.6
  TOP w0.381: U5.B23 v2(39.44,75.5)
  BOTTOM w0.381: 39.72,78.25 39.21,77.74 C382.2 C24.2 39.21,75.74 v2(39.44,75.5)
AVDD_THS: length 4.5
  TOP w0.381: U5.A22 v2(38.64,74.7)
  BOTTOM w0.381: v2(38.64,74.7) 38.06,75.28 38.06,76.09 C24.1 C382.1 38.19,78.12 38.06,78.25
GND_SIGNAL: length 68.3
  TOP w0.254: R155.2 72.48,104.28 v1(72.61,104.16) ; v1(72.74,108.09) 72.86,108.22 73.5,108.22 ; R163.2 76.04,109.24 v1(75.53,108.73)
  TOP w0.381: v1(75.53,104.03) 75.91,103.65 C344.2
  TOP w0.508: v1(73.75,99.96) 73.75,99.46 ER3.1 74.51,99.46 v1(74.51,99.96)
  ART02 w0.635: 44.64,101.06 J8.6 ; J8.6 45.71,102.12 ; J8.6 44.64,103.19 ; J8.6 43.57,102.12 ; 44.64,109.95 J7.6 ; J7.6 45.71,111.01 ; J7.6 44.64,112.08 ; J7.6 43.57,111.01 ; J5.6 34.91,111.01 ; J5.6 33.85,112.08 ; J5.6 32.78,111.01 ; J5.6 33.85,109.95 ; J6.6 33.85,103.19 ; J6.6 32.78,102.12 ; J6.6 34.91,102.12 ; J6.6 33.85,101.06
  ART03 w0.635: J8.6 44.64,103.19 ; J8.6 44.64,101.06 ; J8.6 45.71,102.12 ; J8.6 43.57,102.12 ; J5.6 34.91,111.01 ; J5.6 33.85,112.08 ; J5.6 33.85,109.95 ; J5.6 32.78,111.01 ; J6.6 33.85,103.19 ; J6.6 32.78,102.12 ; J6.6 33.85,101.06 ; J6.6 34.91,102.12 ; 44.64,109.95 J7.6 ; J7.6 45.71,111.01 ; J7.6 44.64,112.08 ; J7.6 43.57,111.01
  BOTTOM w0.254: R168.2 61.36,107.71 v1(61.23,107.58) ; C337.2 v1(58,102.76) ; R157.2 v1(75.61,110.68) ; v1(75.53,107.08) 75.21,107.4 C341.1 ; R166.2 v1(61.23,106.7) ; C349.2 v1(56.99,105.93)
  BOTTOM w0.381: C383.1 v1(60.92,103.39) 60.87,103.34 C336.2 58.95,102.76 v1(58,102.76) ; R167.2 v1(60.92,100.98) ; C335.1 v1(61.18,111.14) ; v1(61.23,107.58) 60.8,107.58 C348.2 60.67,106.7 v1(61.23,106.7) ; v1(75.53,103.14) 75.4,103.01 C338.2 ; v1(75.53,102.25) 75.02,102.25 C339.1 C384.1 ; v1(75.53,108.73) 75.28,108.47 C340.2 ; v1(60.92,99.91) C346.2 58.51,99.91 C347.2 v1(57.24,100.42) ; C385.1 v1(61.18,110.25) 61.11,110.32 C342.2 59.2,110 v1(58,110) C343.2 ; D9.5 v1(78.34,103.39) ; R165.2 v1(75.53,104.03) ; C334.1 v1(60.92,104.28)
P12V_FLT: length 51.1
  TOP w0.508: R57.2 56.35,35.6 55.46,34.71 R101.2 54.26,32.98 53.3,32.02 53.3,31.64 52.42,30.75 52.42,27.83 ; R64.2 v1(19.27,78.5) ; v1(91.57,97.01) 89.14,99.43 82.51,99.43 80.13,97.04 v1(78.22,97.04)
  BOTTOM w0.254: R240.2 v1(78.22,97.04)
  BOTTOM w0.381: R104.2 v1(7.32,43.27)
  BOTTOM w0.508: R73.2 19.78,77.99 v1(19.27,78.5) 15.2,78.5 14.7,77.99 v1(8.09,77.99) ; R188.2 79.72,82.57 87.59,82.57
  vias: v1(2.38,51.58) v1(2.38,50.31) v1(2.38,49.04) v1(2.38,47.13) v1(2.38,45.23) v1(3.01,87.77) v1(3.01,86.5) v1(3.01,84.6) v1(3.01,82.69) v1(3.01,79.26) v1(3.01,77.99) v1(3.01,76.72) v1(3.01,75.45) v1(4.28,99.2) v1(4.28,97.93) v1(4.28,96.92) v1(4.28,91.96) v1(4.28,87.77) v1(4.28,86.5) v1(4.28,84.6) v1(4.28,82.69) v1(4.28,79.26) v1(4.28,77.99) v1(4.28,65.55) v1(4.28,64.28) v1(4.28,51.58) v1(4.28,50.31) v1(4.28,49.04) v1(4.28,47.13) v1(4.28,45.23) v1(4.41,94) v1(5.17,71.39) v1(5.55,99.2) v1(5.55,97.93) v1(5.55,91.71) v1(5.55,84.6) v1(5.55,82.69) v1(5.55,79.26) v1(5.55,77.99) v1(5.55,65.55) v1(5.55,64.28) v1(6.06,71.39) v1(6.19,51.58) v1(6.19,50.31) v1(6.19,49.04) v1(6.19,47.13) v1(6.82,99.2) v1(6.82,97.93) v1(6.82,84.6) v1(6.82,82.69) v1(6.82,79.26) v1(6.82,77.99) v1(6.82,76.72) v1(6.95,95.39) v1(6.95,94.12) v1(6.95,92.85) v1(6.95,91.58) v1(6.95,90.31) v1(6.95,89.04) v1(6.95,87.77) v1(6.95,86.5) v1(8.09,99.2) v1(8.09,97.93) v1(8.09,95.39) v1(8.09,94.12) v1(8.09,92.85) v1(8.09,91.58) v1(8.09,90.31) v1(8.09,89.04) v1(8.09,87.77) v1(8.09,86.5) v1(8.09,84.6) v1(8.09,82.69) v1(8.09,80.53) v1(8.09,79.26) v1(9.24,95.39) v1(9.24,94.12) v1(9.36,99.2) v1(9.36,97.93) v1(9.36,23) v1(9.36,21.1) v1(11.27,23) v1(11.27,21.1) v1(13.17,23) v1(13.17,21.1) v1(26.51,24.91) v1(26.51,23.64) v1(26.51,22.37) v1(26.51,21.1) v1(27.78,21.1) v1(29.05,24.91) v1(29.05,23.64) v1(29.05,22.37) v1(29.05,21.1) v1(30.32,24.91) v1(30.32,23.64) v1(30.32,22.37) v1(30.32,21.1) v1(41.87,25.63) v1(41.87,23.09) v1(43.14,25.63) v1(43.14,23.09) v1(44.41,25.63) v1(44.41,23.09) v1(45.68,25.63) v1(45.68,23.09) v1(46.19,21.1) v1(46.95,25.63) v1(46.95,23.09) v1(48.1,21.1) v1(48.22,25.63) v1(48.22,23.09) v1(49.11,21.1) v1(49.49,25.63) v1(49.49,23.09) v1(50,21.1) v1(50,19.83) v1(50.76,25.63) v1(50.76,23.09) v1(51.27,21.1) v1(51.27,19.83) v1(51.91,23) v1(56.35,22.37) v1(56.35,21.1) v1(56.35,19.83) v1(57.62,22.37) v1(57.62,21.1) v1(61.43,27.07) v1(61.43,26.18) v1(61.43,23) v1(62.7,27.07) v1(62.7,26.18) v1(62.7,23) v1(63.97,27.07) v1(63.97,26.18) v1(63.97,23) v1(65.24,27.07) v1(65.24,26.18) v1(65.24,23) v1(66.51,23) v1(66.77,27.07) v1(66.77,26.18) v1(67.78,27.07) v1(67.78,26.18) v1(67.78,23) v1(69.05,27.07) v1(69.05,26.18) v1(69.05,23) v1(70.32,27.07) v1(70.32,26.18) v1(70.32,23) v1(87.59,78.37) v1(88.48,82.82) v1(88.61,79.64) v1(88.61,78.37) v1(88.61,77.23) v1(89.75,82.82) v1(89.75,79.64) v1(89.75,78.37) v1(89.75,77.23)
V6314_VCC: length 25.6
  TOP w0.381: v1(64.23,85.87) 64.35,85.74 70.45,85.74 72.48,83.71 v1(76.67,83.71)
  BOTTOM w0.254: U13.18 74.75,81.66 75.33,82.24 75.33,82.31 75.83,82.82 C357.2 ; v1(64.23,85.87) 63.41,85.05 63.41,80.43 R213.1 63.72,80.13 63.72,79.9 63.97,79.64 63.97,79.09
  BOTTOM w0.381: C357.2 76.67,83.58 v1(76.67,83.71) 76.8,83.71 77.31,84.22 R140.2
VBUS_5V: length 1.9
  TOP w0.381: R226.2 C380.2 63.46,12.46 v1(63.46,11.72)
  vias: v1(57.37,12.08) v1(58.13,12.08) v1(58.13,11.32) v1(63.44,10.94)
VCC_1V0: length 25
  BOTTOM w0.381: J6.2 40.45,103.65 48.2,103.65 J8.2 52.33,104.73 C337.1 58.38,105.11 C336.1 59.91,105.5 R159.1
VCC_1V8: length 64.3
  TOP w0.381: U5.G23 43.84,75.9 v2(43.65,76.09) ; U5.T23 v2(51.44,75.5) ; U5.Y23 v2(53.84,75.5) U5.W23 ; v2(57.04,75.5) U5.AC23 ; v2(55.44,74.7) U5.AB22 ; U5.N23 v2(48.24,75.5)
  TOP w0.508: v1(68.98,55.64) 68.95,55.67 v1(68.95,56.66) 68.95,56.78 66.13,59.6 66.13,73.02 61.89,77.26 v1(58.64,77.26) 57.75,77.26 v1(57.7,77.21)
  BOTTOM w0.381: U6.2 77.3,51.08 77.69,50.69 77.69,48.91 C392.1 ; FB5.1 C33.2 43.53,76.22 v2(43.65,76.09) ; v2(48.24,75.5) 47.72,76.03 47.72,78.12 47.89,78.3 47.89,79.85 46.32,81.42
  BOTTOM w0.508: R27.1 R29.1 ; R27.1 v1(68.98,55.64) ; R27.1 R26.1 R25.1 R47.1 R175.1 R46.1 R174.1 69.81,49.27 70.32,48.76 76.19,48.76 C23.1 C392.1 ; R29.1 v1(68.95,56.66) ; R29.1 R232.1
  vias: v1(54.19,89.45) v1(54.19,88.61)
VCC_3V3: length 95.9
  TOP w0.254: R225.2 v1(82.39,18.3) ; R221.2 70.32,12.97 v1(70.7,12.59) 71.47,13.35 R224.2
  TOP w0.508: v1(68.71,77.99) 69.05,77.99 69.51,78.45 69.51,81.73 68.67,82.57 65.55,82.57 62.83,85.28 62.83,85.74
  ART02 w0.508: v1(27.85,33.67) 27.83,33.65 v1(27.83,32.65) 27.83,31.97 39.56,20.23 47.72,20.23 48.99,18.96 58.28,18.96 59.15,19.83 62.53,19.83 63.34,19.01 63.34,17.41 62.37,16.45 v1(62.37,15.76) v1(64.58,15.76)
  BOTTOM w0.254: R13.2 v1(84.93,46.37) ; v1(60.92,95.14) R182.2 ; R141.1 76.67,86.5 v1(76.55,86.63) ; R14.2 v1(83.66,46.37) ; U6.19 85.73,51.08 C22.2 v1(85.79,50.31) ; R176.2 v1(82.39,46.37) ; v1(61.05,91.2) 61.18,91.33 R150.2
  BOTTOM w0.305: v1(68.71,77.99) 68.48,77.76 R143.1 ; R177.2 R176.2
  BOTTOM w0.381: R97.2 24.98,35.96 25.44,36.41 26.56,36.41 27.02,35.96 R91.2 R88.2 R81.2 v1(27.85,33.67) ; R97.2 R94.2 ; R97.2 R98.2 R248.2 ; R80.2 v1(27.83,32.65) ; R228.1 R229.1 R230.1 R231.1 70.07,8.91 71.59,10.43 71.59,12.46 R222.2 v1(70.7,12.59)
  vias: v1(57.17,87.92) v1(58.13,88.03) v1(58.08,87.19) v1(69.18,92.6) v1(69.94,92.6) v1(70.83,92.6) v1(70.83,91.58) v1(71.72,92.6) v1(71.72,91.58) v1(83.38,18.33) v1(84.32,18.33) v1(84.34,17.47)
VCC_5V0: length 197.4
  TOP w0.508: v1(61.29,19) v1(62.31,19)
  TOP w0.635: v1(74.26,90.06) v1(75.4,90.06) 77.94,90.06 83.4,84.6 90.01,84.6 91.35,83.25 91.35,59.91 84.67,53.23 84.67,50.43 79.37,45.13 79.37,26.46 74.08,21.17 64.99,21.17 62.82,19 v1(62.31,19)
  ART02 w0.381: v1(11.26,43.3) 9.72,43.3 8.47,42.05 7.02,42.05 v1(6.56,42.51) ; v1(10,36.46) 10.2,36.26 13.5,36.26 17.74,32.02 22.06,32.02 v1(23.16,30.93) 23.16,30.42 23.54,30.04 28.64,30.04 39.28,19.4 47.37,19.4 48.54,18.23 58.99,18.23 59.77,19 v1(61.29,19)
  ART02 w0.508: v1(62.31,19) v1(61.29,19)
  BOTTOM w0.381: v1(6.56,42.51) R105.1 6.44,41.32 6.44,40.02 v1(10,36.46) ; R140.1 78.83,85.74 79.97,86.88 79.97,88.03 80.48,88.53 ; R116.1 11.34,43.3 v1(11.26,43.3) ; R83.1 27.52,38.88 27.14,38.5 R102.2 27.37,38.27 28.59,37.05 28.59,32.5 26.71,30.62 25.11,30.62 24.3,31.44 23.66,31.44 v1(23.16,30.93) R84.2
VCC_N0V5: length 26.6
  BOTTOM w0.381: 58.89,108.73 58.51,108.35 C348.1 57.88,107.71 C349.1 55.21,107.71 53.18,109.74 48.45,109.74 J7.4 45.91,109.74 37.66,109.74 J5.4
VCC_N1V0: length 23.9
  BOTTOM w0.381: R160.1 60.54,112.23 60.42,112.1 C342.1 58.26,112.1 C343.1 50.55,111.85 J7.2 48.45,112.28 40.2,112.28 J5.2
VCC_N5V0: length 31.7
  TOP w0.254: C386.2 v1(72.74,107.2)
  TOP w0.508: v1(75.4,100.85) 75.4,101.36 73.5,103.27 C386.2 74.01,107.2 74.77,107.97 76.55,107.97 78.78,110.2 78.78,111.47 v1(78.83,111.52)
  TOP w0.762: U14.5 69.69,99.84 C333.1 72.86,100.85 v1(75.4,100.85)
  BOTTOM w0.381: C341.2 72.93,107.4 v1(72.74,107.2) 72.55,107.2 71.97,107.78 U17.4 ; U16.4 73.69,100.8 C384.2 C339.2 v1(75.4,100.85) ; D10.5 78.34,110.88 78.07,111.14 C345.2 v1(78.83,111.52)
VCC_P0V5: length 27.1
  BOTTOM w0.381: J6.4 37.66,100.85 45.91,100.85 J8.4 47.72,102.12 48.99,100.85 51.97,100.85 52.54,101.43 C347.1 59.27,101.43 C346.1 60.09,102.25 R169.1
VCC_P5V0: length 29.2
  TOP w0.762: v1(63.79,110.96) 62.96,110.12 62.96,105.17 v1(63.72,104.41) 65.75,102.38 U14.8
  BOTTOM w0.381: C383.2 C334.2 63.52,104.28 63.72,104.48 v1(63.72,104.41) 63.92,104.61 U16.8 68.36,104.61 70.01,106.26 R161.2 ; v1(63.79,110.96) 63.79,110.83 63.21,110.25 C385.2 ; v1(63.79,110.96) 63.6,111.14 C335.2 ; v1(63.79,110.96) 64.42,111.59 U17.8
  vias: v1(64.46,98.39) v1(64.48,97.6)
VDDA_OSC: length 3.4
  TOP w0.381: U5.G22 v2(44.24,74.7)
  BOTTOM w0.381: FB5.2 C25.1 44.41,74.87 v2(44.24,74.7)
VDDA_PLL0: length 11.1
  TOP w0.381: U5.N20 v2(48.24,72.3)
  BOTTOM w0.254: C34.1 49.11,77.87 49.34,77.64 49.34,75.05 48.81,74.51 48.81,72.87 v2(48.24,72.3)
  BOTTOM w0.381: C34.1 C35.2 C36.2 C37.2 49.11,81.85 R234.2
VDDA_PLL1: length 12.9
  TOP w0.381: U5.P20 v2(49.84,72.3)
  ART02 w0.305: v2(49.84,72.3) 49.34,72.8 49.34,74.44 51.96,77.05 52.62,77.05 v1(53.3,77.74)
  BOTTOM w0.381: R235.2 53.74,81.47 C43.2 C40.1 C42.2 C41.2 v1(53.3,77.74)
VSSA_PLL0: length 12.1
  TOP w0.381: U5.N19 v2(48.24,71.5)
  BOTTOM w0.254: C34.2 49.85,77.97 49.85,74.79 49.29,74.23 49.29,72.55 v2(48.24,71.5)
  BOTTOM w0.381: C34.2 C35.1 C36.1 C37.1 50.13,81.93 FB7.1
VSSA_PLL1: length 13.4
  TOP w0.381: U5.P19 v2(49.84,71.5)
  ART02 w0.305: v2(49.84,71.5) 48.86,72.49 48.86,74.77 51.83,77.74 v1(52.29,77.74)
  BOTTOM w0.381: v1(52.29,77.74) C41.1 C42.1 C40.2 C43.1 52.29,82.06 FB9.1
0: length 701.7
  TOP w0.203: R129.1 R131.1 R133.1 R135.1 27.02,37.12 v1(27.27,37.38) ; 25.75,37.99 R99.1 R247.1 R139.1 R137.1 ; v1(14.37,55.64) 14.39,55.67
  TOP w0.254: v1(64.61,14.87) 64.48,14.75 C376.1 C377.1 62.45,14.75 v1(62.32,14.87) ; v1(43.65,91.96) 43.65,91.33 44.54,90.44 44.54,88.53 41.62,85.61 v1(41.62,84.72) ; C18.2 v1(48.61,92.73) v1(48.61,96.79) v1(41.62,96.79) v1(41.62,92.73) C20.2 ; v1(13.66,52.95) 14.39,53.69 14.39,55.67 14.52,55.79 14.52,62.7 16.22,64.4 R59.2 16.22,65.17 16.63,65.57 18.33,65.57 18.58,65.83 ; Q28.2 v1(74.39,8.52) ; C378.1 71.34,18.94 v1(71.59,18.68) ; v1(43.53,84.34) v1(43.53,79.39) 43.53,78.07 ; v1(67.15,80.25) 67.02,80.38 67.02,80.91 ; v1(64.23,18.43) 64.8,17.86 U19.2 ; Q27.2 70.58,10.56 v1(70.83,10.81) ; v1(71.21,7.89) 70.96,8.14 C375.1 ; R203.1 75.66,73.42 v1(75.4,73.17) ; R223.1 C379.1 v1(82.39,17.29)
  TOP w0.305: 51.72,90.95 C352.2 v1(52.42,90.19) ; 42.38,93.36 C20.2 42.38,92.09 ; X1.2 50.39,97.05 ; X1.2 51.72,96.03 ; X1.2 50.39,95.02 ; X1.2 49.06,96.03 ; C18.2 47.84,93.36 ; 51.72,91.84 C351.2 52.42,92.47 v1(52.67,92.73)
  TOP w0.381: v2(43.44,74.7) U5.F22 ; U5.F22 v2(42.64,74.7) ; U5.F22 v2(43.44,73.9) U5.F21 ; v2(57.04,60.3) U5.AC5 v2(56.24,60.3) U5.AB4 U5.AA3 v2(54.64,58.7) U5.Y2 U5.W1 v2(53.04,57.1) ; U5.K20 v2(46.64,73.1) U5.L21 ; v2(38.64,60.3) U5.A5 U5.B6 v2(40.24,61.9) U5.C7 U5.D8 v2(41.84,63.5) U5.E9 U5.G11 v2(44.24,65.9) U5.H12 ; U5.P12 v2(49.04,65.9) U5.N11 U5.M10 v2(47.44,64.3) U5.L9 U5.K8 v2(45.84,62.7) U5.J7 U5.G5 v2(43.44,60.3) U5.F4 U5.E3 v2(41.84,58.7) U5.D2 U5.C1 v2(40.24,57.1) ; v2(38.64,58.7) U5.A3 U5.B4 v2(40.24,60.3) U5.C5 U5.D6 v2(41.84,61.9) U5.E7 U5.G9 v2(44.24,64.3) U5.H10 U5.J11 v2(45.84,65.9) U5.K12 ; v2(38.64,69.1) U5.A15 U5.B14 v2(40.24,67.5) U5.C13 U5.B12 U5.A11 v2(38.64,65.1) ; v2(57.04,63.5) U5.AC9 v2(56.24,63.5) U5.AB8 U5.AA7 v2(54.64,61.9) U5.Y6 U5.W5 v2(53.04,60.3) U5.V4 ; U5.V22 v2(52.24,74.7) ; v2(57.04,69.1) U5.AC15 U5.AB14 v2(55.44,67.5) U5.AA13 U5.Y12 v2(53.84,65.9) 53.84,65.9 U5.W11 v2(53.04,65.1) ; U5.R5 v2(49.84,60.3) U5.P4 U5.N3 v2(48.24,58.7) U5.M2 U5.L1 v2(46.64,57.1) ; v2(52.24,69.1) U5.U15 U5.T16 v2(50.64,69.9) U5.R17 ; v2(57.04,65.1) U5.AC11 v2(56.24,65.1) U5.AB10 U5.AA9 v2(54.64,63.5) U5.Y8 U5.W7 v2(53.04,61.9) ; U5.M20 v2(48.24,73.1) U5.N21 ; U5.L13 v2(46.64,67.5) U5.K14 v2(45.84,68.3) U5.J15 U5.H16 v2(44.24,69.9) U5.G17 U5.E19 v2(41.84,72.3) U5.D20 U5.C21 v2(40.24,73.9) U5.B21 ; v1(27.9,41.67) 26.13,39.89 26.13,37.99 ; U5.N1 v2(48.24,57.1) ; v2(56.24,57.1) U5.AC1 v2(57.04,57.1) ; v2(45.04,74.7) U5.H22 v2(45.04,73.9) U5.J21 ; U5.W13 v2(53.84,67.5) U5.Y14 U5.AA15 v2(55.44,69.1) U5.AB16 U5.AC17 v2(57.04,70.7) ; v2(57.04,61.9) U5.AC7 v2(56.24,61.9) U5.AB6 U5.AA5 v2(54.64,60.3) U5.Y4 U5.W3 v2(53.04,58.7) U5.V2 ; v2(38.64,72.3) U5.A19 U5.B18 v2(40.24,70.7) U5.C17 U5.D16 v2(41.84,69.1) U5.E15 v2(43.44,67.5) U5.G13 43.29,66.55 U5.E11 v2(41.84,65.1) U5.D10 U5.C9 v2(40.24,63.5) U5.B8 U5.A7 v2(38.64,61.9) ; v2(57.04,67.5) U5.AC13 U5.AB12 U5.AA11 v2(54.64,65.1) U5.Y10 U5.W9 v2(53.04,63.5) ; U5.M19 v2(47.44,71.5) ; U5.J13 v2(45.04,67.5) U5.H14 v2(44.24,68.3) U5.G15 U5.E17 v2(41.84,70.7) U5.D18 U5.C19 v2(40.24,72.3) U5.B20 ; U5.H20 v2(45.04,72.3) U5.J19 U5.L17 v2(47.44,69.9) U5.M16 U5.N15 v2(49.04,68.3) U5.P14 ; v2(52.24,63.5) U5.U9 U5.T10 v2(50.64,65.1) U5.R11 U5.P10 v2(49.04,64.3) U5.N9 U5.M8 v2(47.44,62.7) U5.L7 U5.J5 v2(45.04,60.3) U5.H4 U5.G3 v2(43.44,58.7) U5.F2 U5.E1 v2(41.84,57.1) ; U5.G21 v2(43.44,73.1) U5.F20 ; U5.W15 v2(53.84,69.1) U5.Y16 U5.AA17 v2(55.44,70.7) U5.AB18 U5.AC19 v2(57.04,72.3) ; U5.P22 v2(49.84,73.9) ; v2(43.44,57.1) U5.G1 U5.H2 v2(45.04,58.7) U5.J3 U5.K4 v2(46.64,60.3) U5.L5 U5.N7 v2(49.04,62.7) U5.P8 U5.R9 v2(50.64,63.5) U5.T8 U5.U7 v2(52.24,61.9) ; v2(45.04,57.1) U5.J1 U5.K2 v2(46.64,58.7) U5.L3 U5.M4 v2(48.24,60.3) U5.N5 U5.R7 v2(50.64,61.9) ; v2(53.84,74.7) U5.Y22 v2(53.84,73.9) U5.W21 ; v2(41.04,74.7) U5.D22 v2(41.84,73.9) U5.E21 ; U5.T22 v2(51.44,73.9) U5.U21 U5.V20 v2(53.04,72.3) U5.W19 v2(53.84,72.3) U5.Y20 U5.AA21 v2(55.44,73.9) U5.AA22 ; v1(67.53,10.43) 67.53,10.73 66.64,11.62 C381.1 R227.2 ; v2(57.04,74.7) U5.AC22 ; U5.C23 v2(40.24,75.5) ; C380.1 v1(62.83,13.6) ; U5.U3 v2(51.44,58.7) U5.T2 ; U5.U1 v2(51.44,57.1) ; U5.L19 v2(46.64,71.5) ; U5.A13 v2(38.64,67.5) ; v1(68.16,92.6) 68.29,92.73 U14.3 ; v2(49.97,57.13) 50.24,57.4 U5.R1 ; U5.R21 50.64,73.1 ; U5.K22 v2(46.64,74.7) ; U5.R15 v2(50.64,68.3) U5.T14 U5.U13 v2(52.24,67.5) ; U5.M22 v2(48.24,74.7) ; v2(39.44,74.7) U5.B22 v2(40.24,74.7) U5.C22 ; U5.P16 v2(49.04,69.9) ; v2(38.64,57.1) U5.A1 U5.B2 v2(40.24,58.7) U5.C3 U5.D4 v2(41.84,60.3) U5.E5 U5.G7 v2(44.24,62.7) U5.H8 U5.J9 v2(45.84,64.3) U5.K10 U5.L11 v2(47.44,65.9) U5.M12 ; v2(38.64,70.7) U5.A17 U5.B16 v2(40.24,69.1) U5.C15 U5.D14 v2(41.84,67.5) U5.E13 U5.D12 U5.C11 v2(40.24,65.1) U5.B10 U5.A9 v2(38.64,63.5) ; U5.N13 v2(48.24,67.5) U5.M14 v2(47.44,68.3) U5.L15 U5.K16 v2(45.84,69.9) U5.J17 U5.G19 v2(43.44,71.5) ; C253.1 v1(73.5,30.24) ; v2(49.84,67.5) U5.R13 U5.T12 U5.U11 v2(52.24,65.1) ; v2(57.04,58.7) U5.AC3 v2(56.24,58.7) U5.AB2 U5.AA1 v2(54.64,57.1) ; U5.P21 v2(49.84,73.1) ; v2(57.04,73.9) U5.AC21 U5.AB20 v2(55.44,72.3) U5.AA19 U5.Y18 v2(53.84,70.7) U5.W17 U5.U19 v2(51.44,72.3) U5.T20 ; v2(49.84,58.7) U5.R3 U5.T4 v2(51.44,60.3) U5.U5 ; v2(52.24,70.7) U5.U17 ; U5.E22 v2(41.84,74.7) U5.D23 v2(41.04,75.5) ; U5.H23 v2(45.04,75.5) ; U5.A23 v2(38.64,75.5) ; U5.R19 v2(50.64,71.5) ; C250.1 v1(72.23,30.24) ; U5.R20 v2(50.64,72.3)
  TOP w0.508: C256.2 v1(55.59,10.18) ; v1(68.04,98.06) 68.29,98.31 U14.6 ; v1(61.81,96.41) 62.19,96.03 C329.2 ; U9.6 v1(16.73,84.98) ; C255.2 v1(54.07,10.3) ; C264.2 v1(20.16,83.96) ; R59.2 v1(15.46,64.79) ; v1(68.16,96.92) 68.29,97.04 74.77,97.04 75.78,98.06 v1(75.78,98.49)
  TOP w0.635: 26.06,9.34 SW1.3 ; SW1.3 26.06,11.9 ; SW1.3 24.78,10.62 ; SW1.3 27.34,10.62 ; J10.2 19.56,12.13 ; J10.2 16.13,14.11 ; J10.2 17.36,12.28 ; J10.2 18.33,13.95 ; SW1.1 26.01,9.05 ; SW1.1 27.23,7.83 ; SW1.1 26.01,6.61 ; SW1.1 24.79,7.83 ; TP9.1 91.79,106.52 ; TP9.1 90.69,105.43 ; TP9.1 91.79,104.33 ; TP9.1 92.88,105.43 ; 22.25,11.33 J10.3 ; J10.3 22.32,13.65 ; J10.3 24.29,14.88 ; J10.3 24.21,12.56 ; SW1.4 33.55,7.38 ; SW1.4 30.98,7.38 ; SW1.4 32.27,6.1 ; SW1.4 32.27,8.66 ; 82.95,20.97 J2.2 ; J2.2 84.04,19.88 ; J2.2 85.13,20.97 ; J2.2 84.04,22.06 ; 12.28,109.26 TP3.1 ; TP3.1 11.19,110.35 ; TP3.1 12.28,111.45 ; TP3.1 13.38,110.35
  TOP w1.016: 40.48,11.49 J9.2 ; J9.2 43.64,11.49 ; J9.2 42.06,9.91 ; 44.68,11.49 J9.1 ; J9.1 47.84,11.49 ; J9.1 46.26,9.91
  ART02 w0.381: v1(31.97,35.07) 31.97,36.29 31.97,36.29
  ART02 w0.508: v1(31.97,33.92) v1(31.97,35.07)
  ART02 w0.635: 90.69,105.43 TP9.1 ; TP9.1 91.79,106.52 ; TP9.1 92.88,105.43 ; TP9.1 91.79,104.33 ; J11.1 93.26,41.8 ; J11.1 90.57,41.8 ; J11.1 91.91,43.15 ; 17.36,12.28 J10.2 ; J10.2 18.33,13.95 ; J10.2 16.13,14.11 ; J10.2 19.56,12.13 ; SW1.4 33.55,7.38 ; SW1.4 30.98,7.38 ; SW1.4 32.27,6.1 ; SW1.4 32.27,8.66 ; 26.01,6.61 SW1.1 ; SW1.1 24.79,7.83 ; SW1.1 26.01,9.05 ; SW1.1 27.23,7.83 ; 82.95,20.97 J2.2 ; J2.2 85.13,20.97 ; J2.2 84.04,19.88 ; J2.2 84.04,22.06 ; TP3.1 13.38,110.35 ; TP3.1 11.19,110.35 ; TP3.1 12.28,109.26 ; TP3.1 12.28,111.45 ; SW1.3 26.06,11.9 ; SW1.3 27.34,10.62 ; SW1.3 24.78,10.62 ; SW1.3 26.06,9.34 ; 22.32,13.65 J10.3 ; J10.3 24.29,14.88 ; J10.3 24.21,12.56 ; J10.3 22.25,11.33
  ART02 w1.016: 42.06,9.61 J9.2 ; J9.2 40.18,11.49 ; J9.2 42.06,13.37 ; J9.2 43.94,11.49 ; J9.1 44.38,11.49 ; J9.1 48.14,11.49 ; J9.1 46.26,9.61 ; J9.1 46.26,13.37
  ART03 w0.762: 85.66,45.41 TP4.1 ; TP4.1 86.73,44.34 ; TP4.1 86.73,46.47 ; TP4.1 87.8,45.41 ; 31.01,7.38 SW1.4 ; SW1.4 32.27,8.64 ; SW1.4 32.27,6.12 ; SW1.4 33.52,7.38 ; J10.2 19.54,12.14 ; J10.2 17.38,12.3 ; J10.2 16.15,14.09 ; J10.2 18.32,13.93 ; 91.79,104.36 TP9.1 ; TP9.1 90.72,105.43 ; TP9.1 91.79,106.49 ; TP9.1 92.85,105.43 ; 11.22,110.35 TP3.1 ; TP3.1 13.35,110.35 ; TP3.1 12.28,111.42 ; TP3.1 12.28,109.29 ; 26.06,9.36 SW1.3 ; SW1.3 27.32,10.62 ; SW1.3 24.8,10.62 ; SW1.3 26.06,11.88 ; 22.34,13.64 J10.3 ; J10.3 24.28,14.85 ; J10.3 22.26,11.36 ; J10.3 24.19,12.57 ; J9.2 43.87,11.49 ; J9.2 42.06,9.68 ; J9.2 42.06,13.29 ; J9.2 40.26,11.49 ; J11.1 93.23,41.8 ; J11.1 91.91,43.12 ; J11.1 90.59,41.8 ; 82.97,20.97 J2.2 ; J2.2 84.04,22.04 ; J2.2 84.04,19.9 ; J2.2 85.11,20.97 ; 26.01,6.63 SW1.1 ; SW1.1 27.21,7.83 ; SW1.1 26.01,9.02 ; SW1.1 24.82,7.83 ; 44.46,11.49 J9.1 ; J9.1 48.07,11.49 ; J9.1 46.26,13.29 ; J9.1 46.26,9.68
  BOTTOM w0.254: v1(65.37,91.2) 65.17,91.4 Q23.S ; v1(61.81,97.93) 61.89,97.86 C328.2 ; 31.21,37.99 31.21,47.11 31.23,47.13 v1(31.28,47.13) ; C390.1 78.2,98.06 v1(77.82,98.44) ; v1(86.83,93.11) 86.83,93.74 86.96,93.87 U20.4 87.59,93.87 87.85,93.61 v1(87.85,93.11) ; C22.1 v1(86.81,50.33) ; v1(67.15,80.25) 67.12,80.28 R214.1 66.64,80.28 ; v1(61.81,96.41) 61.87,96.41 61.94,96.34 R154.2 ; U6.11 v1(82.01,56.28) ; v1(47.46,87.9) 47.97,87.39 48.35,87.39 ; C13.1 C14.2 75.28,86.83 75.2,86.76 v1(75.15,86.76) ; R241.2 v1(80.61,95.9) ; v1(74.23,82.97) 74.77,83.51 C360.2 ; v1(61.05,93.61) C353.1 ; C391.1 76.57,82.21 76.16,81.8 C357.1 ; R217.1 v1(67.91,79.09) ; v1(78.83,83.71) 77.97,82.84 C358.1
  BOTTOM w0.305: v1(65.07,72.94) 65.04,72.91 C204.2 ; v1(55.72,80.84) 55.11,80.23 R44.2 ; C204.2 63.36,72.91 62.6,72.15 R208.1 R210.1 ; C204.2 v1(63.85,74.13) ; C366.2 v1(70.96,87.65) ; C354.1 v1(60.92,96.28) ; v1(68.54,86.43) 68.8,86.17 C370.1 ; R219.1 65.5,76.72 C359.2 ; Q25.2 52.42,92.98 v1(52.67,92.73) 53.05,92.34 C355.1 ; R243.2 v1(78.07,93.87) ; Q3.2 v1(56.23,95.65)
  BOTTOM w0.381: Q26.2 52.9,89.17 C45.2 ; Q26.2 51.65,88.61 v1(52.09,88.18) ; Q26.2 52.42,89.93 v1(52.42,90.19) ; v1(86.32,36.85) C326.2 v1(87.21,37.73) ; C292.1 R108.1 v1(8.85,40.99) ; v1(10.38,42.56) 10.61,42.56 R75.2 ; C276.1 10.48,45.42 R67.2 ; 22.98,50.21 20.85,50.21 v1(19.85,49.2) R103.1 ; R82.1 v1(17.06,51.34) ; v1(67.4,92.6) 67.4,91.99 C15.2 68.16,91.94 v1(68.16,92.6) ; v1(55.86,92.59) U18.1 55.86,91.4 ; FB7.2 50.38,84.6 v1(50.64,84.85) ; C265.2 v1(12.66,34.43) ; U7.2 57.52,85.97 58.03,85.46 C44.2 58.33,85.44 v1(58.33,84.39) ; v1(43.53,79.39) 43.91,79.01 43.91,78.76 ; C391.1 76.83,82.24 76.83,82.77 v1(76.98,82.92) 77.87,82.92 C358.1 ; C330.2 78.83,86.88 v1(78.7,86.76) ; v1(27.27,37.38) 26.99,37.1 C287.2 ; v1(61.05,65.67) C201.2 v1(63.85,65.67) ; R115.1 11.21,36.95 v1(10.63,36.95) ; v1(64.48,77.87) 64.48,77.36 64.99,76.85 R219.1 ; 20.54,54.12 v1(20.54,55.26) ; C350.2 55.44,87.39 v1(55.36,87.32) ; v1(8.35,46.75) 8.35,46.88 8.98,46.24 8.98,44.77 R118.1 9.37,44.34 R107.2 v1(8.08,44.13) ; v1(77.56,86.76) 76.93,87.39 C387.2 ; FB9.2 v1(52.16,84.85) ; C279.1 R77.2 v1(20.49,31.13) ; v1(15.96,31.07) 15.52,31.52 14.82,30.83
  BOTTOM w0.508: v1(54.7,30.37) 54.7,28.59 54.01,27.9 51.6,27.9 51.15,27.45 ; R122.1 v1(29.3,47.77) ; v1(55.72,80.84) 55.92,81.04 ER2.2 ; v1(88.99,98.57) 89.12,98.44 C331.2 v1(90.26,99.58) ; 18.06,76.47 18.06,74.63 v1(18.38,74.31) ; v1(18.38,69.61) 18.13,69.61 17.62,70.12 ; 14.44,54.12 15.71,54.12 16.09,53.74 16.09,52.59 v1(15.08,51.58) v1(13.81,50.31) ; v1(53.3,98.69) 53.94,99.33 Q24.2
  BOTTOM w0.635: TP3.1 12.28,111.45 ; TP3.1 11.19,110.35 ; TP3.1 12.28,109.26 ; TP3.1 13.38,110.35 ; 90.69,105.43 TP9.1 ; TP9.1 92.88,105.43 ; TP9.1 91.79,104.33 ; TP9.1 91.79,106.52 ; 16.13,14.11 J10.2 ; J10.2 18.33,13.95 ; J10.2 19.56,12.13 ; J10.2 17.36,12.28 ; 22.25,11.33 J10.3 ; J10.3 24.21,12.56 ; J10.3 22.32,13.65 ; J10.3 24.29,14.88 ; 30.98,7.38 SW1.4 ; SW1.4 32.27,8.66 ; SW1.4 33.55,7.38 ; 84.04,19.88 J2.2 ; J2.2 84.04,22.06 ; J2.2 85.13,20.97 ; J2.2 82.95,20.97 ; SW1.1 26.01,9.05 ; SW1.1 24.79,7.83 ; SW1.1 26.01,6.61 ; SW1.1 27.23,7.83 ; 24.78,10.62 SW1.3 ; SW1.3 26.06,11.9 ; SW1.3 26.06,9.34 ; SW1.3 27.34,10.62 ; J11.1 91.91,43.15 ; J11.1 90.57,41.8 ; J11.1 93.26,41.8
  BOTTOM w1.016: 43.94,11.49 J9.2 ; J9.2 42.06,9.61 ; J9.2 40.18,11.49 ; 44.38,11.49 J9.1 ; J9.1 48.14,11.49 ; J9.1 46.26,9.61
  vias: v1(0.85,108.98) v1(0.85,106.44) v1(0.85,103.9) v1(0.85,101.36) v1(0.85,98.82) v1(0.85,96.28) v1(0.85,93.74) v1(0.85,91.2) v1(0.85,88.66) v1(0.85,86.12) v1(0.85,83.58) v1(0.85,81.04) v1(0.85,78.5) v1(0.85,75.96) v1(0.85,73.42) v1(0.85,70.88) v1(0.85,68.34) v1(0.85,65.8) v1(0.85,63.26) v1(0.85,60.72) v1(0.85,58.18) v1(0.85,55.64) v1(0.85,53.1) v1(0.85,50.56) v1(0.85,48.02) v1(0.85,45.48) v1(0.85,44.21) v1(0.85,41.67) v1(0.85,39.13) v1(0.85,36.59) v1(0.85,34.05) v1(0.85,30.24) v1(0.85,26.43) v1(0.85,25.16) v1(1.49,111.39) v1(2,23.13) v1(2.12,96.92) v1(2.12,95.39) v1(2.12,94.12) v1(2.12,91.96) v1(2.12,89.93) v1(3.01,23.64) v1(3.65,21.22) v1(3.77,113.3) v1(4.28,105.55) v1(4.28,103.01) v1(4.28,101.11) v1(5.55,113.55) v1(5.55,21.1) v1(5.81,18.94) v1(7.46,111.27) v1(8.09,113.55) v1(8.09,18.56) v1(8.09,16.53) v1(9.24,15.51) v1(9.87,83.2) v1(9.87,82.06) v1(9.87,79.26) v1(10.25,14.62) v1(10.63,113.55) v1(10.63,111.27) v1(10.63,109.36) v1(10.63,16.02) v1(11.14,47.46) v1(11.19,50.84) v1(11.52,79.26) v1(12.79,12.72) v1(13.17,113.55) v1(13.17,82.69) v1(13.17,79.26) v1(13.81,111.27) v1(14.44,14.11) v1(14.57,82.69) v1(15.08,10.94) v1(15.71,113.55) v1(15.73,39.03) v1(16.45,39.74) v1(16.45,38.31) v1(17.16,40.46) v1(17.16,39.03) v1(17.16,37.59) v1(17.62,111.27) v1(17.88,41.18) v1(17.88,39.74) v1(17.88,38.31) v1(18,9.16) v1(18.25,113.55) v1(18.38,73.04) v1(18.38,71.77) v1(18.38,68.47) v1(18.63,95.9) v1(18.63,94.63) v1(18.63,93.49) v1(18.6,40.46) v1(18.6,39.03) v1(18.6,37.59) v1(18.76,91.33) v1(18.76,90.19) v1(18.76,88.79) v1(19.27,85.11) v1(19.32,39.74) v1(19.32,38.31) v1(19.65,97.17) v1(19.65,95.9) v1(19.65,94.63) v1(20.03,74.31) v1(20.03,73.04) v1(20.03,71.77) v1(20.03,69.61) v1(20.03,68.47) v1(20.04,39.03) v1(20.41,91.33) v1(20.41,90.19) v1(20.41,88.79) v1(20.54,97.17) v1(20.54,95.9) v1(20.54,94.63) v1(20.54,93.49) v1(20.54,85.11) v1(20.79,113.55) v1(20.79,111.27) v1(20.79,14.11) v1(20.79,10.94) v1(21.05,66.18) v1(21.17,7.51) v1(21.3,75.2) v1(21.3,74.31) v1(21.3,73.04) v1(21.3,71.77) v1(21.3,70.63) v1(21.3,69.61) v1(21.3,68.47) v1(21.43,76.34) v1(22.06,96.66) v1(22.06,95.39) v1(22.06,94.12) v1(22.06,91.58) v1(22.06,90.31) v1(22.06,89.04) v1(22.06,87.77) v1(22.06,83.96) v1(22.06,82.69) v1(22.06,81.42) v1(22.06,80.15) v1(22.06,78.88) v1(22.19,66.18) v1(22.57,76.72) v1(22.57,75.58) v1(22.57,74.31) v1(22.57,73.04) v1(22.57,71.77) v1(22.57,70.63) v1(22.57,69.61) v1(22.57,68.47) v1(22.7,82.06) v1(22.7,80.79) v1(22.7,79.52) v1(22.7,78.25) v1(23.08,51.07) v1(23.33,113.55) v1(23.33,96.66) v1(23.33,95.39) v1(23.33,94.12) v1(23.33,91.58) v1(23.33,90.31) v1(23.33,89.04) v1(23.33,87.77) v1(23.33,83.96) v1(23.97,111.27) v1(24.22,5.86) v1(24.35,51.07) v1(24.35,49.04) v1(24.35,47.64) v1(24.35,45.86) v1(24.6,95.39) v1(24.6,94.12) v1(24.6,91.58) v1(24.6,90.31) v1(24.6,89.04) v1(24.6,87.77) v1(24.6,86.5) v1(24.6,85.23) v1(24.6,83.96) v1(25.24,17.03) v1(25.24,15.76) v1(25.24,12.84) v1(25.87,113.55) v1(25.87,94.12) v1(25.87,92.85) v1(25.87,91.58) v1(25.87,90.31) v1(25.87,89.04) v1(25.87,87.77) v1(25.87,86.5) v1(25.87,85.23) v1(26.13,5.22) v1(26.51,111.27) v1(26.51,17.03) v1(26.51,15.76) v1(26.76,51.07) v1(26.76,49.04) v1(26.76,47.77) v1(27.78,17.03) v1(27.78,15.76) v1(28.03,51.07) v1(28.03,49.04) v1(28.03,47.77) v1(28.03,4.46) v1(28.41,113.55) v1(29.05,17.03) v1(29.05,15.76) v1(29.05,13.35) v1(29.3,49.04) v1(29.68,111.27) v1(29.94,3.83) v1(30.95,113.55) v1(31.46,72.15) v1(31.46,70.12) v1(31.46,68.09) v1(31.59,57.93) v1(31.59,56.66) v1(31.59,3.19) v1(32.22,113.55) v1(32.22,72.15) v1(32.22,70.12) v1(32.22,68.09) v1(32.86,57.93) v1(32.86,56.66) v1(32.86,4.59) v1(33.68,30.69) v1(34.13,57.93) v1(34.13,56.66) v1(34.76,113.55) v1(34.83,31.83) v1(34.76,2.43) v1(35.4,12.21) v1(35.4,9.67) v1(35.4,7.76) v1(35.52,25.92) v1(36.03,113.55) v1(36.03,97.3) v1(36.16,51.32) v1(36.41,33.54) v1(36.67,95.39) v1(36.67,93.49) v1(36.92,30.88) v1(37.43,52.97) v1(37.43,51.32) v1(37.81,37.48) v1(37.81,1.79) v1(37.94,97.3) v1(37.94,94.76) v1(37.94,92.22) v1(37.94,12.21) v1(37.94,9.67) v1(37.94,7.76) v1(37.94,4.59) v1(38.06,32.15) v1(38.57,113.55) v1(38.7,51.32) v1(38.83,22.75) v1(38.95,28.72) v1(39.21,31) v1(39.84,7.76) v1(39.97,84.72) v1(39.97,82.82) v1(39.97,81.55) v1(40.6,85.74) v1(40.6,40.4) v1(40.6,39.64) v1(40.73,95.27) v1(40.73,93.87) v1(40.73,92.34) v1(40.73,1.41) v1(40.86,78.76) v1(40.99,77.61) v1(40.99,76.47) v1(41.11,113.55) v1(41.62,82.82) v1(41.62,78.25) v1(41.62,76.98) v1(41.87,40.4) v1(41.87,39.64) v1(42.13,37.28) v1(42.38,7.76) v1(42.38,4.59) v1(43.14,40.4) v1(43.14,39.64) v1(43.14,38.88) v1(43.14,37.28) v1(43.27,90.44) v1(43.65,113.55) v1(44.16,85.49) v1(44.16,1.03) v1(44.41,40.4) v1(44.41,39.64) v1(44.41,38.88) v1(44.41,37.28) v1(44.92,7.76) v1(45.05,95.9) v1(45.05,94.12) v1(45.56,51.45) v1(45.56,37.28) v1(45.68,40.4) v1(45.68,39.64) v1(45.68,38.88) v1(46.19,113.55) v1(46.7,87.14) v1(46.83,52.97) v1(46.83,40.4) v1(46.83,39.64) v1(47.08,0.9) v1(47.46,51.41) v1(47.46,7.76) v1(47.84,40.4) v1(47.84,39.64) v1(47.84,38.88) v1(47.84,37.28) v1(48.1,4.59) v1(48.61,76.85) v1(48.73,113.55) v1(48.86,40.4) v1(48.86,39.64) v1(48.86,38.88) v1(48.86,37.28) v1(49.11,51.45) v1(49.75,1.03) v1(50,9.67) v1(50,7.76) v1(50.13,40.4) v1(50.13,39.64) v1(50.13,38.88) v1(50.13,37.28) v1(50.51,77.36) v1(51.27,113.55) v1(51.27,80.91) v1(51.27,40.4) v1(51.27,39.64) v1(51.27,38.88) v1(51.78,37.99) v1(52.16,12.72) v1(52.54,42.56) v1(52.54,41.16) v1(53.05,12.72) v1(53.05,1.29) v1(53.18,4.59) v1(53.81,113.55) v1(54.57,42.56) v1(54.57,41.16) v1(54.83,52.97) v1(55.21,1.41) v1(56.1,53.99) v1(56.1,52.97) v1(56.35,113.55) v1(56.35,30.37) v1(56.61,42.56) v1(56.61,41.16) v1(56.86,26.3) v1(57.11,30.24) v1(57.37,53.99) v1(57.37,52.97) v1(57.62,33.29) v1(58.51,73.93) v1(58.64,42.56) v1(58.64,41.16) v1(58.89,113.55) v1(60.04,57.04) v1(60.04,38.37) v1(60.04,2.3) v1(60.16,113.55) v1(60.29,40.4) v1(60.42,54.12) v1(60.42,52.97) v1(60.67,42.18) v1(60.67,41.16) v1(61.81,37.38) v1(61.94,87.67) v1(62.07,2.81) v1(62.32,55.13) v1(62.58,17.92) v1(62.7,113.55) v1(62.7,12.46) v1(62.7,11.57) v1(62.83,40.43) v1(62.83,39.66) v1(62.83,38.9) v1(62.83,37.38) v1(63.21,56.02) v1(63.41,9.18) v1(63.59,3.19) v1(64.1,40.43) v1(64.1,39.66) v1(64.1,38.9) v1(64.1,37.38) v1(64.48,57.55) v1(64.48,56.4) v1(64.48,55.13) v1(64.48,53.99) v1(65.12,3.57) v1(65.24,113.55) v1(65.24,37.38) v1(65.37,40.43) v1(65.37,39.66) v1(65.37,38.9) v1(65.88,6.37) v1(66.51,17.92) v1(66.51,16.4) v1(67.4,17.16) v1(67.53,40.4) v1(67.53,39.64) v1(67.53,38.88) v1(67.53,37.48) v1(67.78,113.55) v1(68.16,16.4) v1(68.29,17.92) v1(68.54,40.4) v1(68.54,39.64) v1(68.54,38.88) v1(68.54,37.48) v1(68.67,6.11) v1(68.67,4.97) v1(69.43,14.75) v1(69.81,40.4) v1(69.81,39.64) v1(69.81,38.88) v1(69.81,37.48) v1(69.81,5.35) v1(70.32,113.55) v1(70.32,73.17) v1(70.32,71.9) v1(70.32,70.63) v1(70.32,69.36) v1(70.45,81.68) v1(70.45,80.41) v1(70.45,79.14) v1(70.96,40.4) v1(70.96,39.64) v1(70.96,38.88) v1(70.96,37.48) v1(71.21,5.98) v1(71.59,73.17) v1(71.59,71.9) v1(71.59,70.63) v1(71.59,69.36) v1(71.87,81.68) v1(71.87,80.41) v1(71.87,79.14) v1(72.1,39.89) v1(72.1,38.75) v1(72.61,6.62) v1(72.86,113.55) v1(72.86,73.17) v1(72.86,71.9) v1(72.86,70.63) v1(72.86,69.36) v1(72.86,68.09) v1(72.99,81.68) v1(72.99,80.41) v1(72.99,79.14) v1(72.99,19.19) v1(73.24,39.89) v1(73.24,38.75) v1(73.88,7.25) v1(74.26,39.39) v1(74.26,38.12) v1(74.26,36.85) v1(74.26,35.58) v1(74.26,34.31) v1(74.26,33.04) v1(74.26,31.77) v1(74.26,30.5) v1(74.39,73.12) v1(74.39,71.85) v1(74.39,70.58) v1(74.39,69.31) v1(74.39,68.04) v1(74.39,66.77) v1(75.28,8.02) v1(75.4,113.55) v1(75.4,71.9) v1(75.53,47.39) v1(75.66,21.48) v1(76.55,74.44) v1(76.55,73.17) v1(76.55,71.9) v1(76.72,77.13) v1(76.67,8.78) v1(76.8,98.49) v1(77.23,68.72) v1(77.94,113.55) v1(78.58,74.44) v1(78.58,73.17) v1(78.58,71.9) v1(78.55,68.75) v1(79.09,20.46) v1(79.21,10.43) v1(79.47,46.37) v1(79.59,25.16) v1(79.87,66.67) v1(80.23,77.71) v1(80.48,113.55) v1(80.48,42.94) v1(80.61,79.64) v1(80.61,37.86) v1(80.99,11.57) v1(81.5,79.64) v1(81.88,23.13) v1(82.39,111.27) v1(82.39,109.36) v1(82.51,79.64) v1(82.49,77.64) v1(82.77,39.64) v1(83.02,113.55) v1(83.02,24.91) v1(83.02,23.64) v1(83.66,13.6) v1(83.91,97.17) v1(83.91,95.65) v1(83.91,94.25) v1(84.17,78.32) v1(84.29,24.91) v1(84.8,96.41) v1(84.8,94.88) v1(84.8,34.69) v1(84.93,111.27) v1(84.93,109.36) v1(85.31,42.31) v1(85.31,40.15) v1(85.56,113.55) v1(85.56,97.17) v1(85.56,95.65) v1(85.56,94.25) v1(85.94,43.45) v1(86.2,15.76) v1(86.32,83.33) v1(86.58,78.88) v1(87.47,111.27) v1(87.47,109.36) v1(88.1,113.55) v1(88.48,18.05) v1(89.37,113.55) v1(90.01,111.27) v1(90.01,103.65) v1(90.52,113.43) v1(90.9,20.72) v1(91.91,113.05) v1(91.91,21.99) v1(92.55,107.46) v1(92.93,112.28) v1(93.06,23.38) v1(93.94,110.76) v1(93.92,24.63) v1(94.2,108.73) v1(94.2,107.46) v1(94.2,106.19) v1(94.2,104.92) v1(94.2,102.38) v1(94.2,99.84) v1(94.2,97.3) v1(94.2,94.76) v1(94.2,92.22) v1(94.2,89.68) v1(94.2,87.14) v1(94.2,84.6) v1(94.2,82.06) v1(94.2,79.52) v1(94.2,77.36) v1(94.2,74.44) v1(94.2,71.9) v1(94.2,69.36) v1(94.2,66.82) v1(94.2,64.28) v1(94.2,63.01) v1(94.2,61.74) v1(94.2,59.2) v1(94.2,56.66) v1(94.2,54.12) v1(94.2,51.58) v1(94.2,49.04) v1(94.2,46.5) v1(94.2,43.96) v1(94.2,41.42) v1(94.2,38.88) v1(94.2,36.34) v1(94.2,33.8) v1(94.2,31.26) v1(94.2,29.99) v1(94.2,27.45) v1(94.2,26.18) v2(37.75,67.5)
